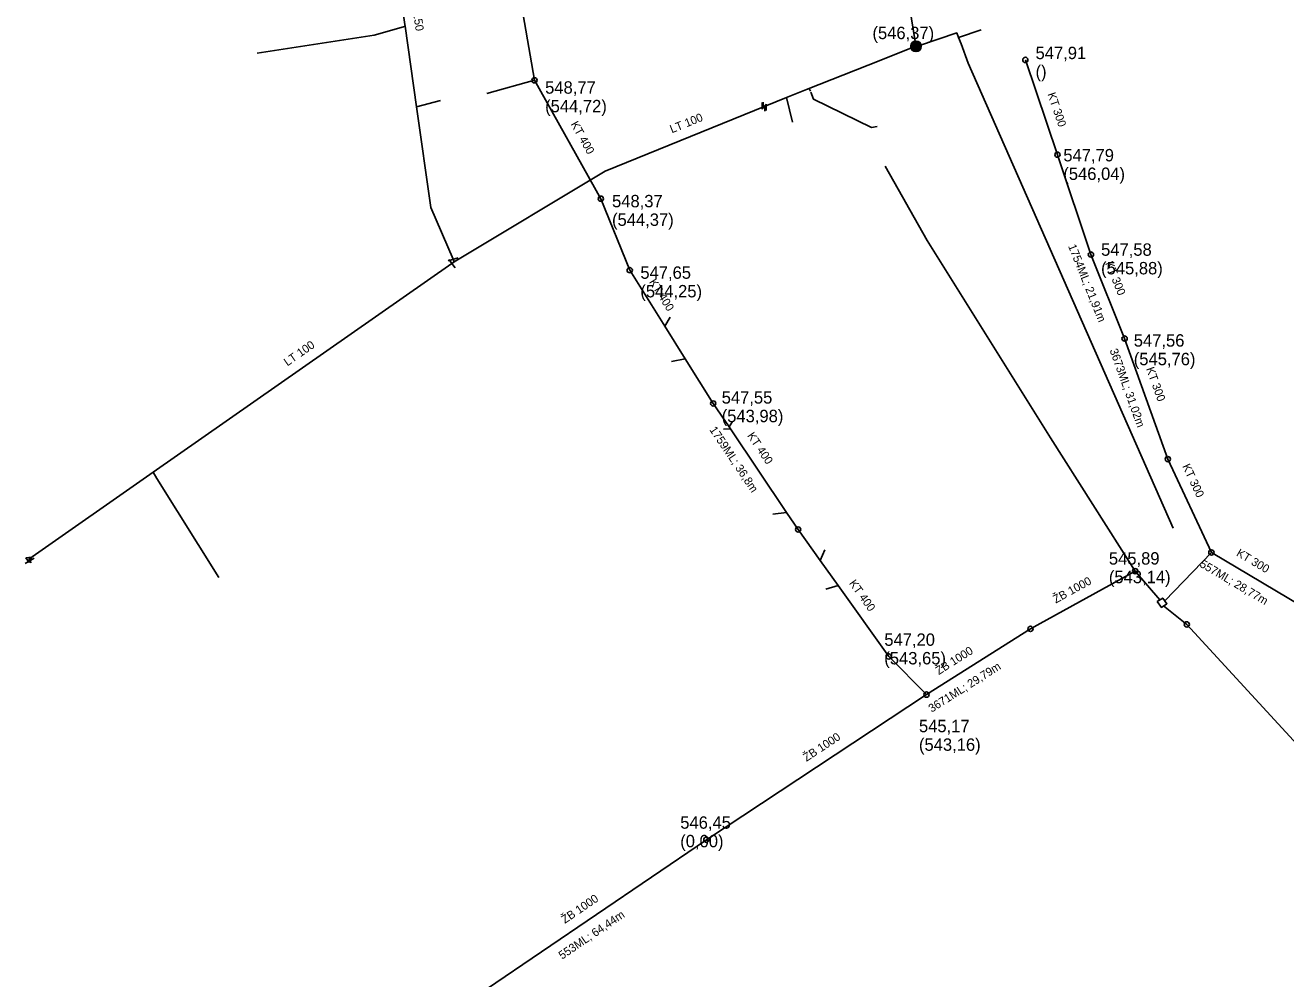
# Model space of a CAD drawing. Extents: x -867696 to -865033, y -1042522 to -1039817.
# Drawn here: x -866301.1 to -865995.7, y -1040292.2 to -1040061.2 of the extents above; entities that cross this region are included whole.
import ezdxf

# ---------------------------------------------------------------- set-up
doc = ezdxf.new("R2010")
doc.units = 0
for name, color, linetype in [('KN - jednotna', 7, 'Continuous'), ('KN - jina', 7, 'Continuous'), ('KN - popis material', 7, 'Continuous'), ('KN - popis ostatni', 7, 'Continuous'), ('KN - popis usek delka', 7, 'Continuous'), ('KN - pripojka', 7, 'Continuous'), ('KN - sachta komora', 7, 'Continuous'), ('Level 1', 7, 'Continuous'), ('V - armatura', 7, 'Continuous'), ('V - hydrant', 7, 'Continuous'), ('V - ostatni', 7, 'Continuous'), ('V - popis material', 7, 'Continuous'), ('V - pripojka', 7, 'Continuous'), ('V - rozvadeci', 7, 'Continuous')]:
    doc.layers.add(name, color=color, linetype=linetype)

# ---------------------------------------------------------------- blocks, each defined once
blk = doc.blocks.new('100.M')
at = {"layer": 'Level 1'}
blk.add_circle((0, 0), 1.27, dxfattribs=at)
blk = doc.blocks.new('160')
at = {"layer": 'Level 1'}
for p, q in [((-1.26, -0.04), (0.05, 1.27)), ((-1.26, -0.06), (0.06, 1.27)), ((-1.26, -0.07), (0.08, 1.27)), ((-1.26, -0.09), (0.09, 1.27)), ((-1.26, 0.11), (-0.12, 1.26)), ((-1.26, 0.1), (-0.1, 1.26)), ((-1.26, 0.08), (-0.09, 1.26)), ((-1.26, 0.07), (-0.07, 1.26)), ((-1.26, 0.06), (-0.06, 1.26)), ((-1.26, 0.04), (-0.04, 1.26)), ((-1.26, 0.03), (-0.03, 1.26)), ((-1.26, 0.01), (-0.01, 1.26)), ((-1.26, 0), (0, 1.26)), ((-1.26, -0.02), (0.02, 1.26)), ((-1.26, -0.03), (0.03, 1.26)), ((-1.26, -0.1), (0.1, 1.26)), ((-1.26, -0.11), (0.12, 1.26)), ((-1.26, -0.13), (0.13, 1.26)), ((-1.26, -0.14), (0.14, 1.26)), ((-1.26, 0.17), (-0.18, 1.25)), ((-1.26, 0.15), (-0.16, 1.25)), ((-1.26, 0.14), (-0.15, 1.25)), ((-1.26, 0.13), (-0.13, 1.25)), ((-1.26, -0.16), (0.15, 1.25)), ((-1.26, -0.17), (0.16, 1.25)), ((-1.25, 0.21), (-0.21, 1.25)), ((-1.25, 0.19), (-0.19, 1.25)), ((-1.25, -0.18), (0.17, 1.25)), ((-1.25, -0.19), (0.19, 1.25)), ((-1.25, -0.2), (0.2, 1.24)), ((-1.25, -0.21), (0.21, 1.24)), ((-1.24, 0.25), (-0.24, 1.25)), ((-1.24, 0.23), (-0.22, 1.25)), ((-1.24, -0.22), (0.22, 1.24)), ((-1.24, -0.24), (0.23, 1.24)), ((-1.24, -0.25), (0.25, 1.24)), ((-1.23, 0.27), (-0.26, 1.24)), ((-1.23, 0.29), (-0.28, 1.23)), ((-1.23, -0.26), (0.26, 1.23)), ((-1.23, -0.27), (0.27, 1.23)), ((-1.23, -0.28), (0.28, 1.23)), ((-1.23, -0.29), (0.29, 1.23)), ((-1.22, 0.3), (-0.3, 1.23)), ((-1.22, 0.32), (-0.32, 1.22)), ((-1.22, -0.3), (0.31, 1.22)), ((-1.22, -0.32), (0.32, 1.22)), ((-1.22, -0.33), (0.33, 1.22)), ((-1.21, -0.34), (0.34, 1.22)), ((-1.21, -0.35), (0.35, 1.22)), ((-1.21, 0.36), (-0.36, 1.21)), ((-1.21, 0.34), (-0.34, 1.21)), ((-1.21, -0.36), (0.36, 1.21)), ((-1.21, -0.37), (0.38, 1.21)), ((-1.2, -0.38), (0.39, 1.21)), ((-1.2, 0.38), (-0.38, 1.2)), ((-1.2, -0.39), (0.4, 1.2)), ((-1.2, -0.41), (0.41, 1.2)), ((-1.2, 0.4), (-0.4, 1.19)), ((-1.19, -0.42), (0.42, 1.2)), ((-1.19, 0.42), (-0.43, 1.19)), ((-1.19, -0.43), (0.43, 1.19)), ((-1.19, -0.44), (0.44, 1.19)), ((-1.19, 0.44), (-0.45, 1.18)), ((-1.19, -0.45), (0.45, 1.18)), ((-1.18, -0.46), (0.46, 1.18)), ((-1.18, 0.46), (-0.47, 1.17)), ((-1.18, -0.47), (0.47, 1.17)), ((-1.17, 0.48), (-0.49, 1.17)), ((-1.17, -0.48), (0.48, 1.17)), ((-1.17, -0.49), (0.49, 1.16)), ((-1.16, 0.51), (-0.51, 1.16)), ((-1.16, -0.5), (0.5, 1.16)), ((-1.16, -0.51), (0.5, 1.16)), ((-1.15, -0.52), (0.51, 1.15)), ((-1.15, -0.53), (0.52, 1.15)), ((-1.14, 0.54), (-0.53, 1.15)), ((-1.14, -0.54), (0.53, 1.14)), ((-1.14, -0.54), (0.54, 1.14)), ((-1.13, -0.55), (0.55, 1.13)), ((-1.13, -0.56), (0.56, 1.13)), ((-1.12, 0.58), (-0.56, 1.14)), ((-1.12, -0.57), (0.57, 1.12)), ((-1.12, -0.58), (0.58, 1.12)), ((-1.11, -0.59), (0.59, 1.11)), ((-1.11, -0.6), (0.6, 1.11)), ((-1.1, 0.61), (-0.6, 1.11)), ((-1.1, -0.61), (0.61, 1.11)), ((-1.1, -0.62), (0.62, 1.1)), ((-1.09, -0.63), (0.63, 1.1)), ((-1.09, 0.64), (-0.64, 1.09)), ((-1.09, -0.64), (0.64, 1.09)), ((-1.08, -0.65), (0.65, 1.09)), ((-1.08, -0.65), (0.66, 1.08)), ((-1.07, -0.66), (0.67, 1.08)), ((-1.07, -0.67), (0.68, 1.07)), ((-1.07, 0.67), (-0.68, 1.06)), ((-1.06, -0.68), (0.69, 1.07)), ((-1.06, -0.69), (0.69, 1.06)), ((-1.05, -0.7), (0.7, 1.05)), ((-1.05, -0.71), (0.71, 1.05)), ((-1.05, 0.7), (-0.71, 1.04)), ((-1.04, -0.72), (0.72, 1.04)), ((-1.04, -0.73), (0.72, 1.04)), ((-1.03, -0.74), (0.73, 1.03)), ((-1.03, -0.75), (0.74, 1.02)), ((-1.03, 0.73), (-0.75, 1.01)), ((-1.02, -0.75), (0.75, 1.02)), ((-1.01, -0.76), (0.76, 1.01)), ((-1.01, -0.77), (0.76, 1)), ((-1, -0.77), (0.77, 1)), ((-0.99, -0.78), (0.78, 0.99)), ((-0.99, -0.79), (0.79, 0.98)), ((-0.98, -0.8), (0.79, 0.98)), ((-0.97, -0.8), (0.8, 0.97)), ((-0.97, -0.81), (0.81, 0.97)), ((-0.96, -0.82), (0.82, 0.96)), ((-0.95, -0.83), (0.83, 0.95)), ((-0.95, -0.83), (0.83, 0.95)), ((-0.94, -0.84), (0.84, 0.94)), ((-0.93, -0.85), (0.85, 0.93)), ((-0.93, -0.86), (0.86, 0.93)), ((-0.92, -0.86), (0.86, 0.92)), ((-0.91, 0.87), (-0.79, 0.99)), ((-0.91, -0.87), (0.87, 0.91)), ((-0.91, -0.88), (0.88, 0.91)), ((-0.9, -0.88), (0.89, 0.9)), ((-0.89, -0.89), (0.89, 0.89)), ((-0.88, -0.9), (0.9, 0.89)), ((-0.88, -0.91), (0.91, 0.88)), ((-0.87, -0.91), (0.92, 0.88)), ((-0.86, -0.92), (0.93, 0.87)), ((-0.86, -0.93), (0.93, 0.86)), ((-0.85, -0.94), (0.94, 0.85)), ((-0.84, -0.94), (0.94, 0.84)), ((-0.84, -0.95), (0.95, 0.84)), ((-0.83, -0.96), (0.96, 0.83)), ((-0.82, -0.96), (0.96, 0.82)), ((-0.82, -0.97), (0.97, 0.81)), ((-0.81, -0.98), (0.97, 0.8)), ((-0.8, -0.98), (0.98, 0.8)), ((-0.79, -0.99), (0.99, 0.79)), ((-0.78, -1), (0.99, 0.78)), ((-0.77, -1), (1, 0.77)), ((-0.77, -1.01), (1, 0.76)), ((-0.76, -1.01), (1.01, 0.75)), ((-0.75, -1.02), (1.02, 0.75)), ((-0.74, -1.02), (1.02, 0.74)), ((-0.73, -1.03), (1.03, 0.73)), ((-0.72, -1.03), (1.03, 0.72)), ((-0.71, -1.04), (1.04, 0.71)), ((-0.71, -1.04), (1.04, 0.71)), ((-0.7, -1.05), (1.05, 0.7)), ((-0.69, -1.06), (1.06, 0.69)), ((-0.68, -1.06), (1.06, 0.68)), ((-0.67, -1.07), (1.07, 0.67)), ((-0.66, -1.07), (1.07, 0.66)), ((-0.65, -1.08), (1.08, 0.66)), ((-0.64, -1.08), (1.09, 0.65)), ((-0.64, -1.09), (1.09, 0.64)), ((-0.63, -1.09), (1.1, 0.63)), ((-0.62, -1.1), (1.1, 0.62)), ((-0.61, -1.11), (1.11, 0.62)), ((-0.6, -1.11), (1.12, 0.61)), ((-0.59, -1.12), (1.12, 0.6)), ((-0.58, -1.12), (1.12, 0.59)), ((-0.58, -1.13), (1.13, 0.58)), ((-0.57, -1.13), (1.13, 0.57)), ((-0.56, -1.14), (1.14, 0.56)), ((-0.55, -1.14), (1.14, 0.55)), ((-0.54, -1.15), (1.14, 0.54)), ((-0.53, -1.15), (1.15, 0.52)), ((-0.52, -1.16), (1.15, 0.51)), ((-0.51, -1.16), (1.16, 0.5)), ((-0.5, -1.16), (1.16, 0.49)), ((-0.49, -1.17), (1.16, 0.48)), ((-0.48, -1.17), (1.17, 0.47)), ((-0.47, -1.17), (1.17, 0.46)), ((-0.46, -1.18), (1.18, 0.45)), ((-0.44, -1.18), (1.18, 0.44)), ((-0.43, -1.18), (1.18, 0.43)), ((-0.42, -1.19), (1.19, 0.42)), ((-0.41, -1.19), (1.19, 0.41)), ((-0.4, -1.19), (1.2, 0.4)), ((-0.39, -1.2), (1.2, 0.39)), ((-0.38, -1.2), (1.2, 0.38)), ((-0.37, -1.2), (1.21, 0.37)), ((-0.36, -1.21), (1.21, 0.36)), ((-0.35, -1.21), (1.22, 0.35)), ((-0.34, -1.22), (1.22, 0.34)), ((-0.33, -1.22), (1.22, 0.33)), ((-0.32, -1.22), (1.23, 0.32)), ((-0.31, -1.23), (1.23, 0.31)), ((-0.3, -1.23), (1.23, 0.3)), ((-0.28, -1.23), (1.23, 0.29)), ((-0.27, -1.24), (1.24, 0.27)), ((-0.26, -1.24), (1.24, 0.26)), ((-0.25, -1.24), (1.24, 0.25)), ((-0.24, -1.25), (1.24, 0.24)), ((-0.23, -1.25), (1.24, 0.22)), ((-0.22, -1.25), (1.24, 0.21)), ((-0.2, -1.25), (1.24, 0.2)), ((-0.19, -1.25), (1.25, 0.19)), ((-0.18, -1.25), (1.25, 0.17)), ((-0.16, -1.25), (1.25, 0.16)), ((-0.15, -1.25), (1.25, 0.15)), ((-0.14, -1.25), (1.25, 0.14)), ((-0.12, -1.25), (1.25, 0.12)), ((-0.11, -1.26), (1.26, 0.11)), ((-0.1, -1.26), (1.26, 0.1)), ((-0.08, -1.26), (1.26, 0.09)), ((-0.07, -1.26), (1.26, 0.07)), ((-0.06, -1.26), (1.26, 0.06)), ((-0.04, -1.26), (1.26, 0.05)), ((-0.03, -1.26), (1.27, 0.04)), ((-0.02, -1.26), (1.27, 0.02)), ((0, -1.26), (1.27, 0.01)), ((0.01, -1.26), (1.27, 0)), ((0.02, -1.26), (1.27, -0.02)), ((0.04, -1.27), (1.27, -0.04)), ((0.05, -1.27), (1.26, -0.05)), ((0.06, -1.27), (1.26, -0.07)), ((0.08, -1.27), (1.26, -0.08)), ((0.09, -1.26), (1.26, -0.1)), ((0.11, -1.26), (1.26, -0.12)), ((0.13, -1.26), (1.25, -0.13)), ((0.15, -1.25), (1.25, -0.15)), ((0.16, -1.25), (1.25, -0.17)), ((0.18, -1.25), (1.25, -0.18)), ((0.2, -1.24), (1.24, -0.2)), ((0.22, -1.24), (1.24, -0.21)), ((0.23, -1.24), (1.24, -0.23)), ((0.25, -1.24), (1.24, -0.25)), ((0.27, -1.23), (1.24, -0.26)), ((0.28, -1.23), (1.23, -0.28)), ((0.3, -1.23), (1.23, -0.3)), ((0.32, -1.22), (1.23, -0.31)), ((0.34, -1.22), (1.22, -0.33)), ((0.35, -1.22), (1.22, -0.35)), ((0.37, -1.21), (1.21, -0.38)), ((0.39, -1.21), (1.2, -0.4)), ((0.42, -1.2), (1.19, -0.43)), ((0.44, -1.18), (1.18, -0.45)), ((0.47, -1.17), (1.17, -0.47)), ((0.5, -1.16), (1.16, -0.5)), ((0.52, -1.15), (1.15, -0.52)), ((0.55, -1.13), (1.14, -0.54)), ((0.58, -1.12), (1.13, -0.57)), ((0.6, -1.11), (1.12, -0.59)), ((0.63, -1.1), (1.11, -0.61)), ((0.65, -1.09), (1.08, -0.66)), ((0.69, -1.06), (1.04, -0.72)), ((0.77, -1), (1, -0.77)), ((0.85, -0.93), (0.96, -0.82))]:
    blk.add_line(p, q, dxfattribs=at)
blk.add_circle((0, 0), 1.27, dxfattribs=at)
blk = doc.blocks.new('147')
at = {"layer": 'Level 1'}
blk.add_line((0, 1.27), (0, -1.27), dxfattribs=at)
blk = doc.blocks.new('111')
at = {"layer": 'Level 1'}
for p, q in [((0.42, 0.72), (-0.83, 0)), ((-0.83, 0), (0.42, -0.72)), ((0.42, -0.72), (0.42, 0.72))]:
    blk.add_line(p, q, dxfattribs=at)
blk = doc.blocks.new('156')
at = {"layer": 'Level 1'}
for p, q in [((-0.07, 1.04), (-0.68, -0.3)), ((0.28, 1.04), (-0.19, 0.08)), ((-0.19, 0.08), (0.7, 0.29)), ((0.7, 0.29), (0.02, -1.08)), ((-0.68, -0.3), (0.21, -0.09)), ((0.21, -0.09), (-0.28, -1.08))]:
    blk.add_line(p, q, dxfattribs=at)
blk = doc.blocks.new('150')
at = {"layer": 'Level 1'}
blk.add_line((0, 1.27), (0, -1.27), dxfattribs=at)

msp = doc.modelspace()

# ---------------------------------------------------------------- linework, layer by layer
at = {"layer": 'KN - jednotna'}
for points in [[(-866177.737, -1040074.575), (-866181.549, -1040052.562)], [(-866051.07, -1040092.59), (-866058.836, -1040069.638)], [(-866161.668, -1040103.248), (-866177.737, -1040074.575)], [(-866042.951, -1040116.782), (-866051.07, -1040092.59)], [(-866154.669, -1040120.575), (-866161.668, -1040103.248)], [(-866034.794, -1040137.115), (-866042.951, -1040116.782)], [(-866134.446, -1040152.834), (-866141.214, -1040142.037), (-866146.192, -1040134.097), (-866154.669, -1040120.575)], [(-866024.32, -1040166.31), (-866034.794, -1040137.115)], [(-866113.889, -1040183.358), (-866116.673, -1040179.225), (-866130.289, -1040159.007), (-866130.617, -1040158.52), (-866134.446, -1040152.834)], [(-866013.768, -1040188.928), (-866024.32, -1040166.31)], [(-866091.945, -1040214.108), (-866104.211, -1040196.919), (-866108.53, -1040190.867), (-866113.889, -1040183.358)], [(-866013.768, -1040188.928), (-866025.088, -1040200.633)], [(-866013.768, -1040188.928), (-865989.019, -1040203.588)], [(-866057.606, -1040207.434), (-866032.24, -1040193.452)], [(-866032.24, -1040193.452), (-866026.238, -1040200.409)], [(-866082.787, -1040223.348), (-866057.606, -1040207.434)], [(-866082.787, -1040223.348), (-866091.945, -1040214.108)], [(-866136.097, -1040258.498), (-866082.787, -1040223.348)], [(-866189.407, -1040294.707), (-866136.097, -1040258.498)]]:
    msp.add_lwpolyline(points, dxfattribs=at)
at = {"layer": 'KN - jina'}
for points in [[(-866025.367, -1040201.886), (-866019.733, -1040206.342)], [(-866019.733, -1040206.342), (-865943.134, -1040289.625)]]:
    msp.add_lwpolyline(points, dxfattribs=at)
at = {"layer": 'KN - pripojka'}
for points in [[(-866177.737, -1040074.575), (-866189.258, -1040077.754)], [(-866032.24, -1040193.452), (-866052.755, -1040161.135), (-866082.64, -1040113.34), (-866092.82, -1040095.38)], [(-866146.192, -1040134.097), (-866144.909, -1040131.95)], [(-866141.214, -1040142.037), (-866144.556, -1040142.705)], [(-866130.617, -1040158.52), (-866129.791, -1040157.205)], [(-866130.289, -1040159.007), (-866131.995, -1040159.101)], [(-866116.673, -1040179.225), (-866120.006, -1040179.684)], [(-866108.53, -1040190.867), (-866107.4, -1040188.323)], [(-866104.211, -1040196.919), (-866107.136, -1040197.843)]]:
    msp.add_lwpolyline(points, dxfattribs=at)
at = {"layer": 'KN - sachta komora'}
msp.add_lwpolyline([(-866026.913, -1040200.835), (-866025.893, -1040202.238), (-866024.561, -1040201.345), (-866025.567, -1040199.985), (-866026.913, -1040200.835)], dxfattribs=at)
at = {"layer": 'V - pripojka'}
for points in [[(-866209.102, -1040061.504), (-866209.475, -1040061.587), (-866216.607, -1040063.653), (-866244.92, -1040067.964)], [(-866085.334, -1040066.345), (-866084.741, -1040066.199), (-866075.472, -1040063.116), (-866075.042, -1040064.18), (-866074.424, -1040065.709), (-866072.729, -1040070.447), (-866023.056, -1040183.009)], [(-866075.042, -1040064.18), (-866069.537, -1040062.368)], [(-866116.697, -1040078.756), (-866115.215, -1040084.714)], [(-866111.197, -1040076.534), (-866110.909, -1040077.22)], [(-866110.796, -1040077.42), (-866110.179, -1040079.183), (-866096.075, -1040085.97), (-866094.753, -1040085.75)], [(-866206.328, -1040080.964), (-866200.491, -1040079.468)], [(-866270.116, -1040169.515), (-866269.197, -1040171.006), (-866254.234, -1040194.974)], [(-866300.236, -1040190.552), (-866299.708, -1040191.464)]]:
    msp.add_lwpolyline(points, dxfattribs=at)
at = {"layer": 'V - rozvadeci'}
for points in [[(-866090.006, -1039969.86), (-866088.268, -1039982.393), (-866098.553, -1039983.847), (-866097.381, -1039991.196), (-866095.963, -1040000.083), (-866092.208, -1040023.741), (-866089.664, -1040039.775), (-866085.38, -1040066.144)], [(-866197.455, -1040117.928), (-866202.847, -1040105.383), (-866206.328, -1040080.964), (-866209.102, -1040061.504), (-866209.17, -1040061.029), (-866211.61, -1040043.912), (-866215.797, -1040004.868)], [(-866085.334, -1040066.345), (-866096.922, -1040070.91), (-866111.832, -1040076.784), (-866116.697, -1040078.756), (-866160.638, -1040096.563), (-866197.189, -1040118.548)], [(-866085.334, -1040066.345), (-866085.38, -1040066.144)], [(-866197.189, -1040118.548), (-866197.455, -1040117.928)], [(-866300.236, -1040190.552), (-866270.116, -1040169.515), (-866197.743, -1040118.967)], [(-866197.189, -1040118.548), (-866197.743, -1040118.967)]]:
    msp.add_lwpolyline(points, dxfattribs=at)

# ---------------------------------------------------------------- block references
at = {"layer": 'KN - sachta komora'}
for p, xscale, yscale, rotation in [((-866058.836, -1040069.638), 0.4999999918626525, 0.4999999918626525, 109.00000122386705), ((-866177.737, -1040074.575), 0.4999999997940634, 0.4999999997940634, 110.00000065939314), ((-866051.07, -1040092.59), 0.4999999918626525, 0.4999999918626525, 109.00000122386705), ((-866161.668, -1040103.248), 0.5000000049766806, 0.5000000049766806, 116.000000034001), ((-866042.951, -1040116.782), 0.4999999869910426, 0.4999999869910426, 111.00000058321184), ((-866154.669, -1040120.575), 0.49999998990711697, 0.49999998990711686, 118.00000133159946), ((-866034.794, -1040137.115), 0.5000000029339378, 0.5000000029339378, 111.99999900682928), ((-866134.446, -1040152.834), 0.4999999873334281, 0.499999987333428, 124.00000045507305), ((-866024.32, -1040166.31), 0.5000000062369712, 0.500000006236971, 112.99999954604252), ((-866113.889, -1040183.358), 0.5000000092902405, 0.5000000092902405, 125.00000023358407), ((-866013.768, -1040188.928), 0.5046025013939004, 0.5046025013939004, -168.88308178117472), ((-866032.24, -1040193.452), 0.5036654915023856, 0.5036654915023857, 167.86109133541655), ((-866057.606, -1040207.434), 0.5000000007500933, 0.5000000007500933, -149.00000017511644), ((-866019.733, -1040206.342), 0.5000000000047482, 0.5000000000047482, 137.9999986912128), ((-866091.945, -1040214.108), 0.5000000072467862, 0.5000000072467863, 130.99999910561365), ((-866082.787, -1040223.348), 0.4999999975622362, 0.4999999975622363, -146.99999872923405), ((-866136.097, -1040258.498), 0.4999999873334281, 0.499999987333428, -145.99999954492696)]:
    msp.add_blockref('100.M', p, dxfattribs=dict(at, xscale=xscale, yscale=yscale, rotation=rotation))
at = {"layer": 'V - armatura'}
for p, xscale, yscale, rotation in [((-866085.38, -1040066.144), 1.0000000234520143, 1.0000000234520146, -78.0000006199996), ((-866197.455, -1040117.928), 0.9999999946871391, 0.9999999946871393, 106.00000024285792), ((-866197.743, -1040118.967), 1.000000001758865, 1.000000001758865, 35.99999933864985)]:
    msp.add_blockref('147', p, dxfattribs=dict(at, xscale=xscale, yscale=yscale, rotation=rotation))
at = {"layer": 'V - hydrant', "xscale": 1.0000000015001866, "yscale": 1.0000000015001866, "rotation": -59.00000017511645}
msp.add_blockref('150', (-866300.022, -1040190.923), dxfattribs=at)
at = {"layer": 'V - ostatni'}
for name, p, xscale, yscale, rotation in [('160', (-866085.334, -1040066.345), 0.9999999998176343, 0.9999999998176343, 63.00000066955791), ('156', (-866122.116, -1040080.952), 1.0225848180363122, 1.0225848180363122, -154.18102564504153), ('111', (-866300.236, -1040190.552), 1.000000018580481, 1.000000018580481, -144.99999976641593)]:
    msp.add_blockref(name, p, dxfattribs=dict(at, xscale=xscale, yscale=yscale, rotation=rotation))

# ---------------------------------------------------------------- texts
at = {"layer": 'KN - popis material'}
for s, rotation, p in [('KT 300', 288.7, (-866053.506, -1040077.902)), ('KT 400', 299.27, (-866169.048, -1040085.171)), ('KT 300', 291.86, (-866039.529, -1040118.864)), ('KT 400', 302.08, (-866150.061, -1040123.407)), ('KT 300', 289.74, (-866029.621, -1040144.428)), ('KT 400', 303.96, (-866126.3, -1040160.633)), ('KT 300', 295.01, (-866020.873, -1040168.019)), ('KT 300', 329.36, (-866007.899, -1040189.615)), ('ŽB 1000', 28.86, (-866051.47, -1040201.311)), ('KT 400', 305.51, (-866101.636, -1040196.396)), ('ŽB 1000', 32.29, (-866079.835, -1040218.643)), ('ŽB 1000', 33.4, (-866111.853, -1040239.638)), ('ŽB 1000', 34.18, (-866170.412, -1040278.903))]:
    msp.add_text(s, height=2, rotation=rotation, dxfattribs=at).set_placement(p)
at = {"layer": 'KN - popis ostatni'}
for s, p in [('(546,37)', (-866095.877, -1040064.599)), ('547,91 ', (-866056.366, -1040069.448)), ('()', (-866056.366, -1040073.948)), ('548,77 ', (-866175.167, -1040077.815)), ('(544,72)', (-866175.167, -1040082.315)), ('547,79 ', (-866049.64, -1040094.21)), ('(546,04)', (-866049.64, -1040098.71)), ('548,37 ', (-866158.958, -1040105.328)), ('(544,37)', (-866158.958, -1040109.828)), ('547,58 ', (-866040.491, -1040117.072)), ('(545,88)', (-866040.491, -1040121.572)), ('547,65 ', (-866152.099, -1040122.645)), ('(544,25)', (-866152.099, -1040127.145)), ('547,56 ', (-866032.574, -1040139.075)), ('(545,76)', (-866032.574, -1040143.575)), ('547,55 ', (-866132.396, -1040152.874)), ('(543,98)', (-866132.396, -1040157.374)), ('545,89 ', (-866038.6, -1040191.862)), ('(543,14)', (-866038.6, -1040196.362)), ('547,20 ', (-866093.005, -1040211.528)), ('(543,65)', (-866093.005, -1040216.028)), ('545,17 ', (-866084.607, -1040232.458)), ('(543,16)', (-866084.607, -1040236.958)), ('546,45 ', (-866142.437, -1040255.828)), ('(0,00)', (-866142.437, -1040260.328))]:
    msp.add_text(s, height=3, dxfattribs=at).set_placement(p)
at = {"layer": 'KN - popis usek delka'}
for s, rotation, p in [('1754ML; 21,91m', 291.86, (-866048.522, -1040114.715)), ('3673ML; 31,02m', 289.74, (-866038.454, -1040139.947)), ('1759ML; 36,8m', 303.96, (-866135.459, -1040159.206)), ('557ML; 28,77m', 329.36, (-866016.786, -1040192.255)), ('3671ML; 29,79m', 32.29, (-866081.528, -1040227.757)), ('553ML; 64,44m', 34.18, (-866171.059, -1040287.562))]:
    msp.add_text(s, height=1.99999, rotation=rotation, dxfattribs=at).set_placement(p)
at = {"layer": 'V - popis material'}
for s, rotation, p in [('LT 150', 278.11, (-866207.676, -1040054.505)), ('LT 100', 22.06, (-866144.467, -1040087.419)), ('LT 100', 34.93, (-866237.606, -1040143.881))]:
    msp.add_text(s, height=2, rotation=rotation, dxfattribs=at).set_placement(p)

doc.saveas('drawing.dxf')
